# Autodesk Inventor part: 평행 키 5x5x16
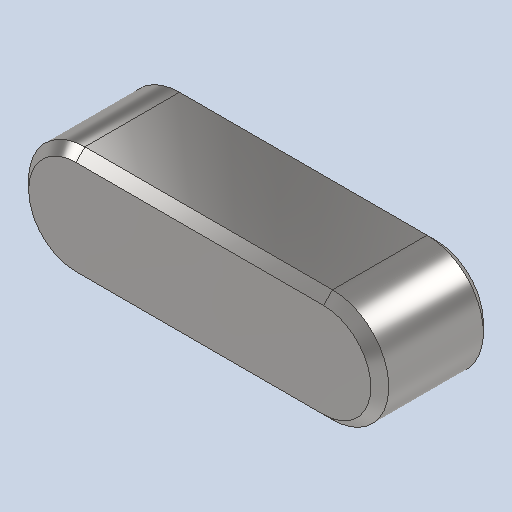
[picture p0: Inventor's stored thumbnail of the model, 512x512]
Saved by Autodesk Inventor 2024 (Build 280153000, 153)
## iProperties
Created: 2026-01
Part Number: 평행 키 5x5x16
Material: 강철, 연강
Description: 키 및 해당 키홈
Document SubType Name: Modeling
Designer: 2-10
Density: 7.85 g/cm^3
Appearance: 기본값
Sending System: Autodesk Inventor 2026
Preprocessor: ST-DEVELOPER v20.1
Author: jhkim
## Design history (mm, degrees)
node "평행 키 5x5x161"
node "솔리드1"
body "Solid1"
